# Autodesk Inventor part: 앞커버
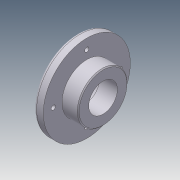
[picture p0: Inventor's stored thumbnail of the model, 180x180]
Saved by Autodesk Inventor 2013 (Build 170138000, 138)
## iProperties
Company: 한국ATC센터
Created: 2014-11
Part Number: 앞커버
Document SubType Name: Modeling
Designer: KYOUNG IL JANG
Density: 2.71 g/cm^3
Material: 알루미늄-6061
Mass: 204.895 g
Surface Area: 201.401 cm^2
Volume: 75.6071 cm^3
Author: KYOUNG IL JANG
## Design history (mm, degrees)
sketch "스케치1"
  geometry: L1 (-13.5, 0)-(13.5, 0); L2 (-13.5, 0)-(-13.5, 45.5); L3 (-13.5, 45.5)-(-3.5, 45.5); L4 (-3.5, 45.5)-(-3.5, 26); L5 (-3.5, 26)-(13.5, 26); L6 (13.5, 26)-(13.5, 0); 2 further points
  constraints: 12 end point, 3 parallel, 2 perpendicular, 1 coincident, 1 horizontal, 1 midpoint
  dimensions: "d0" = 27 distance of L1.start L1.end; "d1" = 91 diameter of L3 L1; "d2" = 52 diameter of L5 L1; "d3" = 10 distance of L2.end L3.end
revolve "회전1" sketch "스케치1" stored, may be unused: angle "d4" = 90 deg
hole "구멍1" diameter "d7" = 30; stored, may be unused: countersink angle "d11" = 90 deg, drill point angle "d13" = 118 deg; dims "d5" = 10, "d6" = 10, "d8" = 6, "d9" = 40, "d10" = 8.3, "d12" = 8
sketch "스케치2"
  geometry: 2 further points
  constraints: 1 vertical alignment
  dimensions: "d14" = 35 distance of point (0, 0) point (0, 35)
hole "구멍2" sketch "스케치2" at (0, 35) diameter "d15" = 4.5; stored, may be unused: countersink angle "d19" = 90 deg, drill point angle "d21" = 118 deg; dims "d16" = 6, "d17" = 8, "d18" = 4.4, "d20" = 8
chamfer "모따기1" distance "d25" = 0.8; stored, may be unused: second distance "d26" = 2, angle "d27" = 30 deg
fillet "모깎기1" dims "d28" = 0.3, "d29" = 3
chamfer "모따기2" distance "d30" = 1; stored, may be unused: second distance "d31" = 2, angle "d32" = 30 deg
node "솔리드1"
pattern_circular "원형 패턴1" dims angle "d23" = 360 deg
